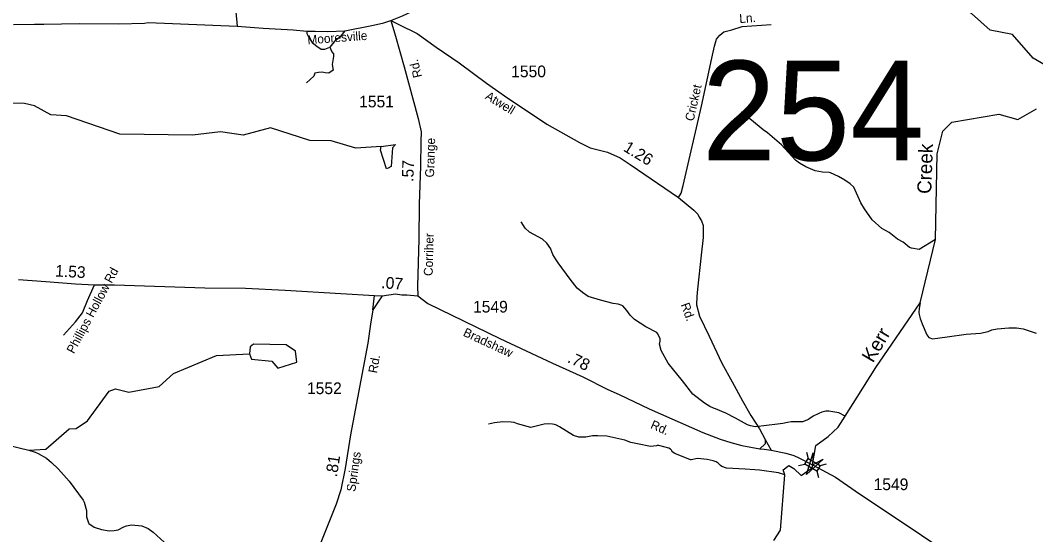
# Model space of a CAD drawing. Extents: x 1473865 to 1648260, y 639067 to 773536.
# Drawn here: x 1494517 to 1505377, y 680616 to 686116 of the extents above; entities that cross this region are included whole.
import ezdxf

# ---------------------------------------------------------------- set-up
doc = ezdxf.new("R2010")
doc.units = 0
for name, color, linetype in [('Exist Hydrographic Creek Single Shore', 7, 'Continuous'), ('Exist Hydrographic Creek Single Shore Label', 7, 'Continuous'), ('Exist Hydrographic Misc Water Feature', 7, 'Continuous'), ('Exist Hydrographic Pond Under 1500 Sq Ft', 7, 'Continuous'), ('Exist Road Non-System Type 51', 7, 'Continuous'), ('Exist Road Non-System Type 51 Label', 7, 'Continuous'), ('Exist Road Primary NC Attributed', 7, 'Continuous'), ('Exist Road Primary NC Label', 7, 'Continuous'), ('Exist Road Secondary Mileage Hundredths English Label', 7, 'Continuous'), ('Exist Road Secondary Structure Standard Bridge Attributed CELL', 7, 'Continuous'), ('Exist Road Secondary Structure Standard Bridge CELL', 7, 'Continuous'), ('Exist Road Secondary Structure Standard Bridge Number Label', 7, 'Continuous'), ('Exist Road Secondary Type 51 Attributed', 7, 'Continuous'), ('Exist Road Secondary Type 51 Label', 7, 'Continuous'), ('Exist Road Secondary Type 51 Number Label', 7, 'Continuous')]:
    doc.layers.add(name, color=color, linetype=linetype)

msp = doc.modelspace()

# ---------------------------------------------------------------- linework, layer by layer
at = {"layer": 'Exist Hydrographic Creek Single Shore'}
for points in [[(1502577, 680554), (1502646, 680664), (1502693, 681257), (1502676, 681310), (1502737, 681355), (1502791, 681322), (1502867, 681248), (1502990, 681333), (1502990, 681362), (1503026, 681570), (1503156, 681665), (1503263, 681766), (1503339, 681882), (1503467, 682085), (1503668, 682403), (1504140, 683094), (1504306, 683772), (1504323, 684687), (1504385, 684932), (1504481, 685028), (1504984, 685113), (1505187, 685056), (1505384, 685171)], [(1490770, 684340), (1490803, 684300), (1490861, 683790), (1491044, 683284), (1491322, 682964), (1491933, 682630), (1492139, 682468), (1492433, 682143), (1492714, 682000), (1492988, 681903), (1493379, 681836), (1493810, 681712), (1494609, 681520), (1494791, 681529), (1495038, 681747), (1495115, 681750), (1495236, 681833), (1495468, 682151), (1495535, 682176), (1495676, 682140), (1496003, 682200), (1496155, 682341), (1496617, 682532), (1496967, 682551)]]:
    msp.add_lwpolyline(points, dxfattribs=at)
at = {"layer": 'Exist Hydrographic Misc Water Feature'}
for points in [[(1498377, 684768), (1498105, 684750), (1497840, 684828), (1497615, 684832), (1497192, 684966), (1496899, 684886), (1496658, 684924), (1496357, 684887), (1495582, 684900), (1495010, 685095), (1494843, 685105), (1494670, 685200), (1494562, 685226), (1494262, 685232), (1493972, 685320), (1493721, 685292), (1493285, 685123), (1493160, 685132), (1492795, 685258), (1492254, 685824), (1492197, 685917), (1491970, 686729), (1491913, 686830)], [(1505581, 685574), (1505350, 685710), (1505129, 685964), (1504888, 686009), (1504691, 686190), (1504410, 686317), (1504228, 686445), (1503962, 686484), (1503681, 686630)], [(1504306, 683772), (1504130, 683665), (1504050, 683678), (1504027, 683686), (1503961, 683744), (1503897, 683776), (1503809, 683847), (1503732, 683888), (1503627, 683984), (1503546, 684100), (1503507, 684163), (1503431, 684333), (1503391, 684368), (1503336, 684405), (1503269, 684444), (1503182, 684485), (1503168, 684490), (1503098, 684491), (1503018, 684508), (1502919, 684550), (1502851, 684588), (1502808, 684622), (1502657, 684783), (1502509, 684914), (1502462, 684943), (1502336, 685049), (1502226, 685135)], [(1498377, 684768), (1498531, 684789), (1498497, 684754), (1498483, 684552), (1498452, 684534), (1498435, 684527), (1498370, 684727), (1498377, 684768)], [(1503339, 681882), (1503271, 681917), (1503163, 681935), (1503132, 681936), (1503091, 681927), (1503059, 681913), (1502995, 681883), (1502949, 681852), (1502946, 681847), (1502883, 681824), (1502762, 681823), (1502721, 681816), (1502673, 681805), (1502617, 681798), (1502381, 681770), (1502325, 681779), (1502294, 681790), (1502166, 681862), (1502063, 681916), (1501952, 681962), (1501932, 681967), (1501893, 681987), (1501835, 682021), (1501711, 682119), (1501600, 682261), (1501445, 682451), (1501372, 682585), (1501353, 682653), (1501361, 682685), (1501362, 682709), (1501335, 682765), (1501323, 682779), (1501208, 682840), (1501086, 682918), (1501038, 682962), (1501005, 683013), (1500960, 683062), (1500944, 683070), (1500911, 683081), (1500857, 683086), (1500721, 683125), (1500590, 683163), (1500529, 683205), (1500474, 683250), (1500397, 683347), (1500269, 683523), (1500247, 683553), (1500214, 683610), (1500190, 683669), (1500191, 683674), (1500148, 683733), (1500103, 683774), (1500010, 683827), (1499963, 683850), (1499917, 683895), (1499873, 683960)], [(1504140, 683094), (1504131, 683034), (1504128, 682993), (1504130, 682969), (1504141, 682928), (1504164, 682872), (1504214, 682751), (1504235, 682724), (1504273, 682710), (1504430, 682733)], [(1504430, 682733), (1504632, 682759), (1504788, 682771), (1504867, 682787), (1504907, 682806), (1504963, 682817), (1505089, 682827), (1505171, 682827), (1505243, 682816), (1505382, 682769)], [(1502693, 681257), (1502626, 681278), (1502424, 681306), (1502372, 681309), (1502270, 681315), (1502069, 681328), (1502021, 681345), (1502005, 681356), (1501982, 681380), (1501958, 681394), (1501926, 681407), (1501864, 681420), (1501758, 681432), (1501693, 681415), (1501686, 681415), (1501516, 681483), (1501490, 681503), (1501484, 681515), (1501471, 681531), (1501453, 681542), (1501345, 681570), (1501329, 681570), (1501321, 681566), (1501257, 681559), (1501118, 681586), (1501046, 681603), (1500984, 681625), (1500791, 681668), (1500695, 681672), (1500635, 681671), (1500567, 681659), (1500491, 681658), (1500433, 681675), (1500285, 681770), (1500253, 681786), (1500229, 681795), (1500208, 681799), (1500170, 681802), (1500121, 681797), (1499977, 681763), (1499834, 681802), (1499798, 681815), (1499766, 681819), (1499678, 681821), (1499590, 681811), (1499526, 681796)], [(1494609, 681520), (1494677, 681497), (1494709, 681483), (1494796, 681433), (1494851, 681388), (1494922, 681321), (1495039, 681189), (1495188, 680986), (1495199, 680962), (1495226, 680873), (1495225, 680805), (1495245, 680743), (1495251, 680737), (1495307, 680696), (1495386, 680670), (1495466, 680657), (1495522, 680660), (1495562, 680669), (1495624, 680700), (1495651, 680709), (1495707, 680720), (1495815, 680710), (1495886, 680681), (1495937, 680644), (1496095, 680501)]]:
    msp.add_lwpolyline(points, dxfattribs=at)
at = {"layer": 'Exist Hydrographic Pond Under 1500 Sq Ft'}
msp.add_lwpolyline([(1496967, 682551), (1496991, 682491), (1497208, 682471), (1497273, 682397), (1497474, 682459), (1497460, 682577), (1497361, 682645), (1497011, 682652), (1496977, 682626), (1496967, 682551)], dxfattribs=at)
at = {"layer": 'Exist Road Non-System Type 51'}
msp.add_line((1498286, 683019), (1498305, 683174), dxfattribs=at)
for points in [[(1497988, 686004), (1497935, 685936), (1497873, 685885), (1497841, 685848), (1497827, 685829)], [(1501555, 684220), (1501585, 684269), (1501608, 684348), (1501801, 685199), (1501914, 685710), (1501941, 685841), (1501963, 685913), (1501997, 685958), (1502043, 685992), (1502126, 686015), (1502239, 686049), (1502549, 686072)], [(1497582, 686001), (1497582, 685974), (1497601, 685939), (1497639, 685877), (1497690, 685840), (1497733, 685807), (1497773, 685807), (1497827, 685829)], [(1497827, 685829), (1497849, 685778), (1497867, 685756), (1497865, 685729), (1497851, 685643), (1497862, 685584), (1497816, 685552), (1497776, 685554), (1497746, 685562), (1497706, 685557), (1497666, 685549), (1497655, 685519), (1497577, 685449)], [(1494978, 682750), (1495106, 682890), (1495182, 682987), (1495237, 683119), (1495309, 683288)], [(1502485, 681632), (1502484, 681588), (1502428, 681535)]]:
    msp.add_lwpolyline(points, dxfattribs=at)
at = {"layer": 'Exist Road Primary NC Attributed'}
for points in [[(1498479, 686113), (1498605, 686164), (1498752, 686231), (1498864, 686316), (1498944, 686379)], [(1496836, 686053), (1497116, 686032), (1497436, 686015), (1497582, 686001), (1497670, 686000), (1497805, 685996), (1497988, 686004), (1498296, 686063), (1498404, 686089), (1498479, 686113)], [(1494446, 686072), (1494670, 686075), (1494768, 686075), (1495145, 686080), (1495569, 686077), (1495844, 686085), (1495885, 686092), (1496836, 686053)]]:
    msp.add_lwpolyline(points, dxfattribs=at)
at = {"layer": 'Exist Road Secondary Structure Standard Bridge Attributed CELL'}
msp.add_lwpolyline([(1503103, 681425), (1502925, 681258), (1502996, 681492), (1502990, 681362)], close=True, dxfattribs=at)
at = {"layer": 'Exist Road Secondary Structure Standard Bridge CELL'}
for p, q in [((1502925, 681499), (1502942, 681432)), ((1502840, 681354), (1502906, 681371)), ((1503072, 681355), (1503139, 681372)), ((1503037, 681295), (1503054, 681229))]:
    msp.add_line(p, q, dxfattribs=at)
msp.add_lwpolyline([(1502942, 681432), (1503072, 681355), (1503037, 681294), (1502906, 681371)], close=True, dxfattribs=at)
at = {"layer": 'Exist Road Secondary Type 51 Attributed'}
for points in [[(1495960, 690703), (1495989, 690473), (1496047, 690091), (1496085, 689835), (1496113, 689629), (1496137, 689555), (1496151, 689509), (1496195, 689372), (1496297, 689168), (1496375, 689023), (1496453, 688870), (1496540, 688679), (1496604, 688539), (1496674, 688083), (1496706, 687914), (1496738, 687681), (1496794, 686872), (1496800, 686808), (1496806, 686742), (1496804, 686679), (1496822, 686206), (1496836, 686053)], [(1498479, 686113), (1498530, 685947), (1498622, 685619), (1498773, 685065), (1498803, 684924), (1498799, 684820), (1498797, 684558), (1498784, 684149), (1498779, 683777), (1498766, 683273), (1498770, 683170)], [(1498479, 686113), (1498567, 686070), (1498762, 685975), (1498964, 685827), (1499212, 685661), (1499502, 685444), (1499730, 685283), (1499930, 685152), (1500148, 685006), (1500499, 684809), (1500612, 684753), (1500699, 684732), (1500798, 684705), (1500931, 684647), (1501039, 684575), (1501555, 684220), (1501721, 684084), (1501763, 684042), (1501777, 684011), (1501803, 683973), (1501819, 683923), (1501821, 683864), (1501822, 683794), (1501799, 683603), (1501759, 683242), (1501754, 683162), (1501748, 683074), (1501781, 682953), (1501885, 682739), (1502021, 682451), (1502129, 682250), (1502242, 682047), (1502329, 681890), (1502423, 681747), (1502485, 681632), (1502546, 681521)], [(1494499, 683343), (1494790, 683323), (1495107, 683298), (1495309, 683288), (1495525, 683288), (1496492, 683257), (1496926, 683251), (1497349, 683230), (1497946, 683194), (1498305, 683174), (1498387, 683171)], [(1498387, 683171), (1498529, 683190), (1498597, 683182), (1498652, 683180), (1498770, 683170)], [(1498387, 683171), (1498286, 683019), (1498263, 682866), (1498234, 682662), (1498049, 681685), (1497993, 681324), (1497944, 681096), (1497894, 680941), (1497730, 680532), (1497576, 680137), (1497529, 680011), (1497477, 679746), (1497422, 679323), (1497378, 679058)], [(1498770, 683170), (1498876, 683086), (1499647, 682712), (1500210, 682451), (1500534, 682303), (1500800, 682168), (1500923, 682115), (1501242, 681963), (1501815, 681707), (1502002, 681638), (1502115, 681600), (1502233, 681570), (1502428, 681535), (1502471, 681530), (1502546, 681521)], [(1502546, 681521), (1502706, 681488), (1502790, 681463), (1502842, 681438), (1502990, 681362)], [(1502990, 681362), (1503235, 681230), (1503492, 681054), (1504034, 680694), (1504275, 680528), (1504472, 680415), (1504639, 680330), (1504812, 680253), (1504955, 680197), (1505281, 680092), (1505898, 679912), (1506187, 679824), (1506844, 679638), (1507135, 679565), (1507332, 679538), (1507500, 679531), (1507816, 679550), (1508261, 679581), (1508439, 679600)]]:
    msp.add_lwpolyline(points, dxfattribs=at)

# ---------------------------------------------------------------- texts
at = {"layer": 'Exist Hydrographic Creek Single Shore Label'}
for s, rotation, p in [('Creek', 88.0052, (1504259, 684258)), ('Kerr', 59.3272, (1503636, 682445))]:
    msp.add_text(s, height=150, rotation=rotation, dxfattribs=at).set_placement(p)
at = {"layer": 'Exist Road Non-System Type 51 Label'}
for s, rotation, p in [('Ln.', 3.9236, (1502210, 686086)), ('Cricket', 77.4401, (1501718, 685031)), ('Phillips Hollow Rd', 61.8091, (1495090, 682544))]:
    msp.add_text(s, height=95, rotation=rotation, dxfattribs=at).set_placement(p)
at = {"layer": 'Exist Road Primary NC Label'}
msp.add_text('Mooresville', height=95, rotation=4.2993, dxfattribs=at).set_placement((1497591, 685859))
at = {"layer": 'Exist Road Secondary Mileage Hundredths English Label'}
for s, rotation, p in [('1.26', 328.5554, (1500957, 684726)), ('.57', 88.2288, (1498721, 684387)), ('1.53', 356.7688, (1494887, 683377)), ('.07', 355.2213, (1498374, 683253)), ('.78', 334.4631, (1500361, 682464)), ('.81', 81.2016, (1497903, 681227))]:
    msp.add_text(s, height=125, rotation=rotation, dxfattribs=at).set_placement(p)
at = {"layer": 'Exist Road Secondary Structure Standard Bridge Number Label'}
msp.add_text('254', height=1066.3, dxfattribs=at).set_placement((1501806, 684618))
at = {"layer": 'Exist Road Secondary Type 51 Label'}
for s, rotation, p in [('Rd.', 103.9337, (1498815, 685514)), ('Atwell', 328.5554, (1499481, 685281)), ('Grange', 88.2288, (1498941, 684434)), ('Corriher', 88.6164, (1498927, 683381)), ('Rd.', 289.7496, (1501580, 683076)), ('Bradshaw', 335.1217, (1499245, 682746)), ('Rd.', 79.6636, (1498331, 682337)), ('Rd.', 336.5425, (1501249, 681757)), ('Springs', 81.9096, (1498099, 681070))]:
    msp.add_text(s, height=95, rotation=rotation, dxfattribs=at).set_placement(p)
at = {"layer": 'Exist Road Secondary Type 51 Number Label'}
for s, p in [('1550', (1499767, 685507)), ('1551', (1498141, 685185)), ('1549', (1499359, 682991)), ('1552', (1497583, 682119)), ('1549', (1503643, 681092))]:
    msp.add_text(s, height=125, dxfattribs=at).set_placement(p)

doc.saveas('drawing.dxf')
